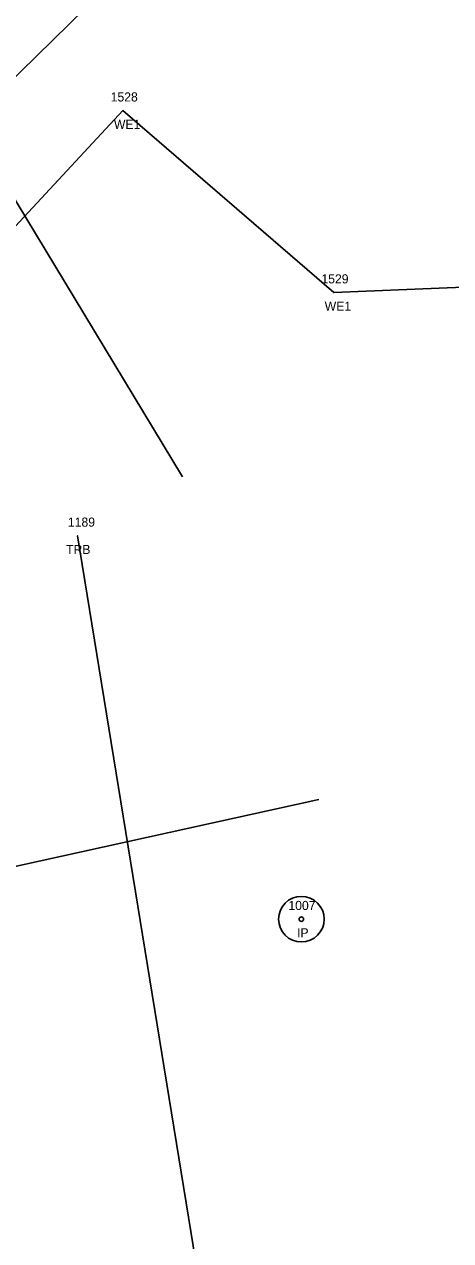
# Model space of a CAD drawing. Extents: x 2522090 to 2524658, y 882711 to 887512.
# Drawn here: x 2523856.5 to 2523903.3, y 884993.3 to 885126.7 of the extents above; entities that cross this region are included whole.
import ezdxf

# ---------------------------------------------------------------- set-up
doc = ezdxf.new("R2010")
doc.units = 0
for name, color, linetype in [('RD_EX_DV_Prop_txCode', 7, 'Continuous'), ('RD_EX_DV_PropPin', 7, 'Continuous'), ('RD_EX_H2O', 7, 'Continuous'), ('RD_EX_H2O_txCode', 7, 'Continuous'), ('RD_EX_VEG', 7, 'Continuous'), ('RD_EX_VEG_txCode', 7, 'Continuous'), ('RD_PD_PatLn5', 7, 'Continuous'), ('RD_PD_PatLn6', 7, 'Continuous'), ('RD_SMD_Locator', 7, 'Continuous')]:
    doc.layers.add(name, color=color, linetype=linetype)

msp = doc.modelspace()

# ---------------------------------------------------------------- linework, layer by layer
at = {"layer": 'RD_EX_DV_PropPin'}
for radius in [2.5, 0.25]:
    msp.add_circle((2523886.89, 885028.52), radius, dxfattribs=at)
at = {"layer": 'RD_EX_H2O'}
for points in [[(2523582.82, 884766.34), (2523598.11, 884856.98), (2523627.59, 884901.75), (2523623.76, 884928.28), (2523586.58, 884955.43), (2523600.94, 884974.12), (2523633.05, 884997.68), (2523679.17, 885037.05), (2523744.72, 885076.89), (2523769.38, 885099), (2523825.47, 885108.66), (2523825.47, 885108.66), (2523845.24, 885110.83), (2523890.25, 885154.93), (2523858.43, 885178.04), (2523850.81, 885196.93), (2523892.51, 885249.74), (2523936.89, 885290.09), (2523980.86, 885285.47), (2524009.06, 885269.77), (2524037.39, 885280.09)], [(2523827.83, 885106), (2523850.3, 885098.92), (2523867.33, 885117.19), (2523890.44, 885097.24), (2523927.79, 885098.78), (2523966.35, 885109.5), (2523978.17, 885083.37)]]:
    msp.add_lwpolyline(points, dxfattribs=at)
at = {"layer": 'RD_EX_VEG'}
msp.add_lwpolyline([(2523998.75, 884575.96), (2523966.17, 884559.06), (2523924.93, 884771.45), (2523880.33, 884960.16), (2523862.36, 885070.56)], dxfattribs=at)
at = {"layer": 'RD_PD_PatLn5'}
msp.add_line((2523888.8, 885041.64), (2523732.54, 885007.24), dxfattribs=at)
at = {"layer": 'RD_PD_PatLn6'}
msp.add_line((2523791.15, 885213.98), (2523873.84, 885077.01), dxfattribs=at)
at = {"layer": 'RD_SMD_Locator'}
for centre in [(2523867.33, 885117.19), (2523890.44, 885097.24), (2523862.36, 885070.56)]:
    msp.add_circle(centre, 0.001, dxfattribs=at)

# ---------------------------------------------------------------- texts
at = {"layer": 'RD_EX_DV_Prop_txCode'}
for s, p in [('1007', (2523885.47, 885029.52)), ('IP', (2523886.42, 885026.52))]:
    msp.add_text(s, height=1, dxfattribs=at).set_placement(p)
at = {"layer": 'RD_EX_H2O_txCode'}
for s, p in [('1528', (2523865.98, 885118.19)), ('WE1', (2523866.34, 885115.19)), ('1529', (2523889.09, 885098.24)), ('WE1', (2523889.45, 885095.24))]:
    msp.add_text(s, height=1, dxfattribs=at).set_placement(p)
at = {"layer": 'RD_EX_VEG_txCode'}
for s, p in [('1189', (2523861.29, 885071.56)), ('TRB', (2523861.09, 885068.56))]:
    msp.add_text(s, height=1, dxfattribs=at).set_placement(p)

doc.saveas('drawing.dxf')
